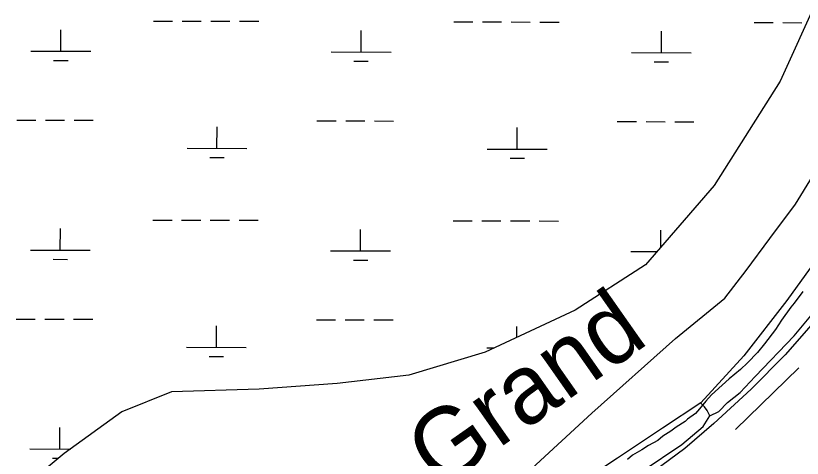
# Model space of a CAD drawing. Extents: x 3172297 to 3210190, y 958463 to 983887.
# Drawn here: x 3177171 to 3178485, y 978656 to 979396 of the extents above; entities that cross this region are included whole.
import ezdxf

# ---------------------------------------------------------------- set-up
doc = ezdxf.new("R2010")
doc.units = 0
for name, color, linetype in [('V-RIVR-IDEN', 7, 'Continuous'), ('V-ROAD-CNTR', 7, 'Continuous'), ('V-SITE-VEGE', 7, 'Continuous'), ('V-TOPO-SHOR', 7, 'Continuous'), ('V-WETL-SWMP', 7, 'Continuous')]:
    doc.layers.add(name, color=color, linetype=linetype)

msp = doc.modelspace()

# ---------------------------------------------------------------- linework, layer by layer
at = {"layer": 'V-ROAD-CNTR'}
msp.add_lwpolyline([(3178512.2, 978892.1), (3178456.9, 978829.2), (3178399.8, 978771.6), (3178337.5, 978714.3), (3178289, 978672.3), (3178212.2, 978615.8), (3178106.1, 978563.2), (3177987.7, 978509.3), (3177895, 978473.7), (3177792.7, 978440.9), (3177720.5, 978416.3), (3177664.5, 978396.7), (3177630.2, 978377.9), (3177589.8, 978353), (3177554.2, 978328.4), (3177507.7, 978289.8), (3177441.9, 978221), (3177336.2, 978100.7), (3177228.9, 977980.6), (3177139.7, 977884.7)], dxfattribs=at)
at = {"layer": 'V-SITE-VEGE'}
for p, q in [((3178486.2, 978935), (3178472, 978915.6)), ((3178472, 978915.6), (3178466.5, 978908.6)), ((3178466.5, 978908.6), (3178450.7, 978886.8)), ((3178450.7, 978886.8), (3178440.5, 978871.3)), ((3178440.5, 978871.3), (3178422.4, 978847.2)), ((3178422.4, 978847.2), (3178410.6, 978833.2)), ((3178410.6, 978833.2), (3178394, 978815.4)), ((3178394, 978815.4), (3178382.3, 978804.5)), ((3178382.3, 978804.5), (3178363.4, 978789)), ((3178363.4, 978789), (3178351.6, 978778.2)), ((3178351.6, 978778.2), (3178333.6, 978761.9)), ((3178333.6, 978761.9), (3178324.1, 978751.8)), ((3178324.1, 978751.8), (3178313.9, 978738.6)), ((3178313.9, 978738.6), (3178306.8, 978730.8)), ((3178293.5, 978721.6), (3178289.6, 978717.7)), ((3178306.8, 978730.8), (3178293.5, 978721.6)), ((3178274.7, 978708.4), (3178266, 978701.4)), ((3178289.6, 978717.7), (3178274.7, 978708.4)), ((3178252.7, 978692.9), (3178244.1, 978686)), ((3178266, 978701.4), (3178252.7, 978692.9)), ((3178244.1, 978686), (3178228.4, 978677.5)), ((3178217.4, 978670.5), (3178201.7, 978661.3)), ((3178228.4, 978677.5), (3178217.4, 978670.5)), ((3178201.7, 978661.3), (3178193.1, 978654.3))]:
    msp.add_line(p, q, dxfattribs=at)
at = {"layer": 'V-TOPO-SHOR'}
msp.add_line((3178479.6, 978807.5), (3178374, 978704.2), dxfattribs=at)
for points in [[(3178330.8, 978727.1), (3178346, 978734.2), (3178360.3, 978749.3), (3178381.8, 978766.2), (3178406.8, 978792.9), (3178472.2, 978860.6), (3178530.4, 978931), (3178568.9, 978989.8), (3178717.7, 979208.2), (3178744.5, 979251.9), (3178783, 979294.6), (3178818, 979341), (3178867.2, 979394.4), (3178894.1, 979427.4), (3178899.4, 979434.5), (3178945.1, 979485.3)], [(3177165.3, 978348.3), (3177233.2, 978405.3), (3177301.3, 978472.9), (3177383.5, 978504.9), (3177426.4, 978519), (3177465.7, 978536.8), (3177508.6, 978543.8), (3177558.5, 978543.7), (3177601.4, 978547.2), (3177651.4, 978550.6), (3177733.5, 978550.4), (3177901.4, 978571.4), (3178033.7, 978639), (3178134, 978731.6), (3178273.5, 978856.2), (3178355.8, 978923.8), (3178391.7, 978970.2), (3178431.1, 979023.7), (3178474.1, 979080.7), (3178502.7, 979127), (3178542.1, 979173.4), (3178552.9, 979191.2), (3178570.8, 979209), (3178692.8, 979433.7)], [(3178588.4, 979098.3), (3178459.4, 978920), (3178387.7, 978827.4), (3178316.1, 978749), (3178251.7, 978706.3), (3178176.6, 978656.5), (3178101.5, 978606.7)], [(3177368.8, 978161.6), (3177412.7, 978216), (3177477.1, 978290.8), (3177514.7, 978318.4), (3177559.4, 978352.2), (3177628.2, 978384.2), (3177695.3, 978409.9), (3177774.8, 978445.4), (3177823, 978459.6), (3177911.5, 978490.6), (3178045.6, 978543.9), (3178122.4, 978579.4), (3178172.5, 978605.1), (3178218.1, 978634.5), (3178284.3, 978679), (3178320, 978709.2), (3178330.8, 978727.1), (3178326.4, 978736), (3178321.9, 978742.3), (3178314.8, 978749.4)]]:
    msp.add_lwpolyline(points, dxfattribs=at)
at = {"layer": 'V-WETL-SWMP'}
for p, q in [((3178577.3, 979571.3), (3178448.8, 979286.7)), ((3177401, 979386.9), (3177433, 979386.8)), ((3177449, 979386.8), (3177481, 979386.7)), ((3177497, 979386.7), (3177529, 979386.6)), ((3177545, 979386.5), (3177577, 979386.5)), ((3177902.9, 979385.7), (3177934.9, 979385.6)), ((3177950.9, 979385.5), (3177982.9, 979385.5)), ((3177998.9, 979385.4), (3178030.9, 979385.3)), ((3178046.9, 979385.3), (3178078.9, 979385.2)), ((3178404.8, 979384.4), (3178436.8, 979384.3)), ((3178452.8, 979384.3), (3178484.8, 979384.2)), ((3177246.3, 979336.6), (3177246.4, 979372.5)), ((3177748.2, 979335.3), (3177748.3, 979371.3)), ((3178250, 979334.1), (3178250.1, 979370.1)), ((3177196.3, 979336.7), (3177296.3, 979336.4)), ((3177698.2, 979335.4), (3177798.2, 979335.2)), ((3178200, 979334.2), (3178300, 979334)), ((3177234.3, 979321.2), (3177258.3, 979321.1)), ((3177736.1, 979319.9), (3177760.1, 979319.9)), ((3178238, 979318.7), (3178262, 979318.6)), ((3178448.8, 979286.7), (3178338.3, 979111.9)), ((3177172.6, 979221.4), (3177204.6, 979221.3)), ((3177220.6, 979221.3), (3177252.6, 979221.2)), ((3177268.6, 979221.1), (3177300.6, 979221.1)), ((3177674.4, 979220.1), (3177706.4, 979220.1)), ((3177722.4, 979220), (3177754.4, 979219.9)), ((3177770.4, 979219.9), (3177802.4, 979219.8)), ((3178176.3, 979218.9), (3178208.3, 979218.8)), ((3178224.3, 979218.8), (3178256.3, 979218.7)), ((3178272.3, 979218.7), (3178304.3, 979218.6)), ((3177507.3, 979174.1), (3177507.4, 979210.1)), ((3178009.1, 979172.9), (3178009.2, 979208.9)), ((3177457.3, 979174.3), (3177557.3, 979174)), ((3177959.1, 979173), (3178059.1, 979172.8)), ((3177495.2, 979158.8), (3177519.2, 979158.7)), ((3177997.1, 979157.5), (3178021.1, 979157.5)), ((3178338.3, 979111.9), (3178223.4, 978979.2)), ((3177400.1, 979054.4), (3177432.1, 979054.3)), ((3177448.1, 979054.3), (3177480.1, 979054.2)), ((3177496.1, 979054.2), (3177528.1, 979054.1)), ((3177544.1, 979054), (3177576.1, 979054)), ((3177901.9, 979053.2), (3177933.9, 979053.1)), ((3177949.9, 979053), (3177981.9, 979053)), ((3177997.9, 979052.9), (3178029.9, 979052.8)), ((3178045.9, 979052.8), (3178077.9, 979052.7)), ((3177245.3, 979004.1), (3177245.5, 979040.1)), ((3177747.2, 979002.8), (3177747.3, 979038.8)), ((3178249.1, 979008.9), (3178249.2, 979037.6)), ((3177195.4, 979004.2), (3177295.3, 979004)), ((3177697.2, 979003), (3177797.2, 979002.7)), ((3178199.1, 979001.7), (3178242.8, 979001.6)), ((3177233.3, 978988.7), (3177257.3, 978988.6)), ((3177735.2, 978987.4), (3177759.2, 978987.4)), ((3178223.4, 978979.2), (3178105.8, 978903.5)), ((3178105.8, 978903.5), (3177955.4, 978833.5)), ((3177171.6, 978888.9), (3177203.6, 978888.8)), ((3177219.6, 978888.8), (3177251.6, 978888.7)), ((3177267.6, 978888.7), (3177299.6, 978888.6)), ((3177506.3, 978841.7), (3177506.4, 978877.6)), ((3177673.5, 978887.6), (3177705.5, 978887.6)), ((3177721.5, 978887.5), (3177753.5, 978887.5)), ((3177769.5, 978887.4), (3177801.5, 978887.3)), ((3178008.2, 978858.1), (3178008.3, 978876.4)), ((3177456.3, 978841.8), (3177556.3, 978841.5)), ((3177958.2, 978840.5), (3177970.5, 978840.5)), ((3177494.2, 978826.3), (3177518.2, 978826.2)), ((3177955.4, 978833.5), (3177827.9, 978795.3)), ((3177827.9, 978795.3), (3177708.4, 978781.2)), ((3177578, 978771.9), (3177431.2, 978767.3)), ((3177708.4, 978781.2), (3177578, 978771.9)), ((3177431.2, 978767.3), (3177348.2, 978733.5)), ((3177348.2, 978733.5), (3177251.7, 978663.9)), ((3177244.4, 978671.6), (3177244.5, 978707.6)), ((3177194.4, 978671.7), (3177262.3, 978671.5)), ((3177251.7, 978663.9), (3177155.1, 978584.2)), ((3177232.3, 978656.2), (3177242.3, 978656.2))]:
    msp.add_line(p, q, dxfattribs=at)

# ---------------------------------------------------------------- texts
at = {"layer": 'V-RIVR-IDEN'}
msp.add_text('Grand', height=116, rotation=35.0399, dxfattribs=at).set_placement((3177878.6, 978602.3))

doc.saveas('drawing.dxf')
